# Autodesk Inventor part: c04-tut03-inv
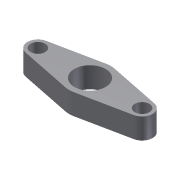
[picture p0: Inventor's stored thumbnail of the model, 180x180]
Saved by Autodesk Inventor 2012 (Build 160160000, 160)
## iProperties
Created: 2008-01
Part Number: c04-tut03-inv
Document SubType Name: Modeling
Designer: CADSoft
Density: 1 g/cm^3
Material: Default
Author: CADSoft
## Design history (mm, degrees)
sketch "Sketch1"
  geometry: L1 (-26, 4.899)-(-2, 9.798); L2 (2, 9.798)-(26, 4.899); L3 (26, -4.899)-(2, -9.798); L4 (-26, -4.899)-(-2, -9.798); C1 r 3.5 at (-25, 0); C2 r 3.5 at (25, 0); C3 r 7.5 at (0, 0); A1 r 5 centre (-25, 0) between (-26, 4.899) and (-26, -4.899); A2 r 5 centre (25, 0) between (26, -4.899) and (26, 4.899); A3 r 10 centre (0, 0) between (-2, -9.798) and (2, -9.798); A4 r 10 centre (0, 0) between (2, 9.798) and (-2, 9.798); 1 further point
  constraints: 8 end point, 8 point on circle, 8 tangent, 7 centre point, 4 coincident, 2 equal radius, 2 horizontal alignment, 1 equal length
  dimensions: "d0" = 50 distance of C2.centre C1.centre; "d1" = 7 diameter of C1; "d2" = 5 radius of A1; "d3" = 10 radius of A4; "d4" = 10 radius of A3; "d5" = 15 diameter of C3; "d6" = 25 distance of A1.centre point (0, 0) (derived)
extrude "Extrusion1" new body sketch "Sketch1" distance "d7" = 10; taper "d8" = 0 deg
body "Solid1"
